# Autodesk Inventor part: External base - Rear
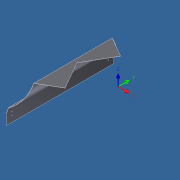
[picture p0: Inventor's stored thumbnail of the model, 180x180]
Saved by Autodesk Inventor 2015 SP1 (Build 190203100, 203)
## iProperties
Category: Mechanical Engineering Drawing and Design - CADD
Manager: Fábio Ricardo de Oliveira Souza
Company: SENAI - Serviço Nacional de Aprendizagem Industrial
Created: 2011-06
Part Number: External base - Rear
Material: Steel
Description: Stainless Steel (DIN- X6CrNiTi18-10)
Document SubType Name: Sheet Metal
Designer: Guilherme Augusto Franco de Souza
Engineer: George Geraldo de Oliveia Silva
Authority: Fábio Ricardo de Oliveira Soza
Density: 7.85 g/cm^3
Sheet Metal Rule: Default_mm
Sheet Metal Width: 336,603 mm
Sheet Metal Length: 597,500 mm
Sheet Metal Area: 201120,218 mm^2
Flat Pattern Width: 33.6603 cm
Flat Pattern Length: 59.75 cm
Flat Pattern Area: 2011.2 cm^2
Appearance: Machined 02
Subject: WorldSkill 2011 - London, England
Author: Guilherme Augusto Franco de Souza
Revision Number: 00
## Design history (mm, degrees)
sketch "Sketch1"
  geometry: L1 (-253, 219.104)-(-253, -219.104); L2 (-253, -219.104)-(126.5, -219.104); L3 (126.5, -219.104)-(253, 0); L4 (253, 0)-(126.5, 219.104); L5 (-253, 219.104)-(126.5, 219.104); L6 (-230.94, 0)-(-115.47, 200); L7 (-115.47, 200)-(115.47, 200); L8 (115.47, 200)-(230.94, 0); L9 (230.94, 0)-(115.47, -200); L10 (115.47, -200)-(-115.47, -200); L11 (-115.47, -200)-(-230.94, 0); A1 r 253 centre (0, 0) between (126.5, -219.104) and (253, 0); 2 further points
  constraints: 22 end point, 3 point on circle, 2 coincident, 2 horizontal alignment, 2 parallel, 1 centre point, 1 equal length, 1 perpendicular, 1 tangent, 1 vertical, 13 other
  dimensions: "d0" = 506 diameter of A1; "d1" = 200 distance from line of point (0, 0) L10
patch "Boundary Patch1" sketch "Sketch1"
sketch "Sketch2"
  geometry: L1 (-219.104, 0)-(-300, -140.115); L2 (-300, -140.115)-(-300, -200); 2 further points
  constraints: 4 end point, 1 vertical
  dimensions: "d3" = 30 deg angle of L2 L1; "d4" = 300 distance from line of point (0, 0) L2; "d26" = 200 vertical distance of point (0, 0) L2.end
extrude_surface "ExtrusionSrf1" sketch "Sketch2" dims "d5" = 650, "d6" = 0
mirror "Mirror1"
sketch "Sketch3"
  geometry: L1 (325, -140.115)-(325, -200) reference; L2 (325, -120)-(325, -140.115); A1 r 136 centre (389, 0) between (253, 0) and (325, -120); 1 further point
  constraints: 2 end point, 2 point on circle, 1 centre point, 1 collinear, 1 horizontal alignment, 1 vertical alignment
  dimensions: "d7" = 120 vertical distance of A1.start L2.start
extrude_surface "ExtrusionSrf3" sketch "Sketch3" dims "d8" = 600, "d9" = 0
feature "Trim1"
feature "Trim2"
feature "Trim3"
feature "Trim4"
sketch "Sketch4"
  geometry: L1 (-325, -200)-(-325, -140.115) reference; L2 (-325, -140.115)-(-253, 0); 1 further point
  constraints: 2 end point
extrude_surface "ExtrusionSrf4" sketch "Sketch4" dims "d10" = 600, "d11" = 0
workplane "Work Plane1"
feature "Trim5"
feature "Trim6"
workplane "Work Plane2"
feature "Trim7"
feature "Trim8"
patch "Boundary Patch2" dims "d12" = 0, "d13" = 0, "d14" = 0, "d15" = 0
patch "Boundary Patch3" dims "d16" = 0, "d17" = 0, "d18" = 0, "d19" = 0
sketch "Sketch5"
  geometry: L1 (-202, -200)-(-202, -138); L2 (202, -200)-(202, -138); L3 (-300, -200)-(300, -200) reference; A1 r 449.042 centre (0, -539.042) between (202, -138) and (-202, -138); 1 further point
  constraints: 4 end point, 2 parallel, 2 point on circle, 1 centre point, 1 horizontal alignment, 1 point on line, 1 vertical, 1 vertical alignment
  dimensions: "d21" = 62 distance of L1.start L1.end; "d22" = 404 distance between parallel lines of L2 L1; "d23" = 110 distance edge to line of A1 L3
extrude_surface "ExtrusionSrf5" sketch "Sketch5" dims "d24" = 600, "d25" = 0
feature "Trim9"
feature "Stitch Surface1"
sketch "Sketch16"
  geometry: L1 (177, -200)-(177, -138); L2 (177, -138)-(112, -73); L3 (112, -73)-(-112, -73); L4 (-112, -73)-(-177, -138); L5 (-177, -138)-(-177, -200); L6 (325, -200)-(-325, -200) reference; 1 further point
  constraints: 10 end point, 2 equal length, 1 horizontal alignment, 1 parallel, 1 perpendicular, 1 point on line, 1 vertical
  dimensions: "d68" = 354 distance between parallel lines of L5 L1; "d69" = 177 distance from line of point (0, 0) L1 (= 0.5 x d68); "d70" = 127 distance between parallel lines of L6 L3; "d71" = 62 distance of L4.end L5.end; "d72" = 224 distance of L2.end L3.end
extrude_surface "ExtrusionSrf6" sketch "Sketch16" dims "d73" = 600, "d74" = 0
feature "Trim10"
feature "Trim11"
sketch "Sketch19"
  geometry: L1 (126.5, -218.854)-(-232.948, -218.854); L2 (-232.948, -218.854)-(-232.948, -219.354); L3 (-232.948, -219.354)-(126.5, -219.354); L4 (126.5, -219.354)-(126.5, -218.854); 2 further points
  constraints: 8 end point, 2 parallel, 1 coincident, 1 horizontal, 1 midpoint, 1 perpendicular
  dimensions: "d102" = 0.5 distance of L3.end L1.start
extrude_surface "ExtrusionSrf7" sketch "Sketch19" dims "d103" = 200, "d104" = 0
feature "Trim12"
sketch "Sketch20"
  geometry: L1 (357.44, 219.104)-(241.97, 419.104) reference; L2 (379.5, 438.209)-(268.08, 373.881); 1 further point
  constraints: 2 end point, 1 perpendicular, 1 point on line
extrude_surface "ExtrusionSrf8" sketch "Sketch20" dims "d105" = 10, "d106" = 0
sketch "Sketch21"
  geometry: L1 (241.97, 19.104)-(357.44, 219.104) reference; L2 (379.5, 0)-(268.08, 64.328); 1 further point
  constraints: 2 end point, 1 perpendicular, 1 point on line
extrude_surface "ExtrusionSrf9" sketch "Sketch21" dims "d107" = 10, "d108" = 0
split "Split2"
split "Split3"
fillet "Fillet2" dims "d113" = 1.25
fillet "Fillet3" dims "d114" = 1.25
delete_face "Delete Face3"
delete_face "Delete Face4"
delete_face "Delete Face5"
delete_face "Delete Face6"
delete_face "Delete Face7"
thicken "Thicken2" dims "d115" = 1, "d116" = 1
feature "Rip14" dims "d117" = 0.5 (= 0.5 x GapSize)
mirror "Mirror6"
node "Unfold1"
sketch "Sketch24"
  geometry: L1 (-1.078, -0.285)-(-1.078, 436.48) reference; L2 (-0.261, -0.285)-(-1.078, -0.285) reference; A1 r 2.111 centre (-0.018, -2.111) between (0, 0) and (-1.078, -0.285); 2 further points
  constraints: 2 point on circle, 1 centre point, 3 other
cut "Cut10" sketch "Sketch24" dims "d118" = 1 (= Thickness), "d119" = 0
mirror "Mirror7"
node "Refold1"
node "Hole1"
node "Hole2"
body "Solid2"
body "Srf1"
body "Srf2"
body "Srf3"
body "Srf4"
body "Srf5"
body "Srf6"
body "Srf7"
body "Srf8"
body "Srf9"
body "Srf10"
body "Srf11"
body "Srf12"
body "Srf13"
sketch "Sketch25"
  geometry: 2 further points
hole "Hole4" sketch "Sketch25" diameter "d126" = 3.4; stored, may be unused: countersink angle "d130" = 90 deg, drill point angle "d132" = 0 deg; dims "d127" = 6, "d128" = 4, "d129" = 2, "d131" = 8
sketch "Sketch26"
  geometry: 2 further points
hole "Hole5" sketch "Sketch26" diameter "d133" = 3.4; stored, may be unused: countersink angle "d137" = 90 deg, drill point angle "d139" = 0 deg; dims "d134" = 6, "d135" = 4, "d136" = 2, "d138" = 8
extrude_surface "ExtrusionSrf2"
feature "Definition1"
other parameters: "Thickness" = 1 (derived), "BendRadius" = 1 (= Thickness), "BendReliefWidth" = 1 (= Thickness), "BendReliefDepth" = 0.5 (= 0.5 x Thickness), "CornerReliefSize" = 4 (= 4 x Thickness), "SeamGap" = 0.01, "MinimumRemnant" = 2 (= 2 x Thickness), "TransitionRadius" = 1 (= BendRadius), "JacobiRadiusSize" = 1 (= BendRadius), "GapSize" = 1 (= Thickness), "d120" = 0, "d121" = 0, "d122" = 0, "d123" = 0, "d124" = 0, "d125" = 0, "BendRadius" = 1, "BendReliefDepth" = 0.5, "BendReliefWidth" = 1, "CornerReliefSize" = 4, "GapSize" = 1, "JacobiRadiusSize" = 1, "MinimumRemnant" = 2, "Thickness" = 1, "TransitionRadius" = 1
